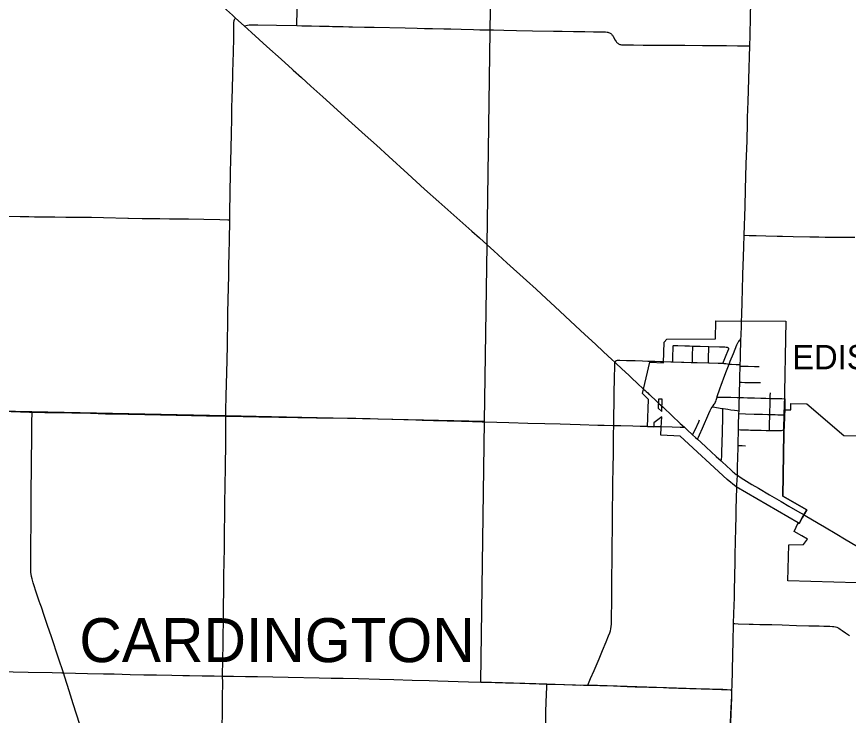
# Model space of a CAD drawing. Extents: x 9078 to 9739, y 4248 to 4966.
# Drawn here: x 9264.8 to 9349.9, y 4628.2 to 4699.7 of the extents above; entities that cross this region are included whole.
import ezdxf

# ---------------------------------------------------------------- set-up
doc = ezdxf.new("R2010")
doc.units = 0
for name, color, linetype in [('GM_X_City_Street', 7, 'Continuous'), ('GM_X_Corporation', 7, 'Continuous'), ('GM_X_Corporation_Text', 7, 'Continuous'), ('GM_X_County_Road', 7, 'Continuous'), ('GM_X_State_Route', 7, 'Continuous'), ('GM_X_Township', 7, 'Continuous'), ('GM_X_Township_Road', 7, 'Continuous'), ('GM_X_Township_Text', 7, 'Continuous')]:
    doc.layers.add(name, color=color, linetype=linetype)

msp = doc.modelspace()

# ---------------------------------------------------------------- linework, layer by layer
at = {"layer": 'GM_X_City_Street'}
for points in [[(9338.904, 4666.691), (9338.915, 4666.982), (9338.956, 4668.127), (9338.963, 4668.547)], [(9337.689, 4664.123), (9337.806, 4664.403), (9338.137, 4665.214), (9338.487, 4666.069), (9338.585, 4666.294), (9338.624, 4666.366), (9338.669, 4666.434), (9338.748, 4666.533), (9338.813, 4666.611), (9338.904, 4666.691)], [(9338.832, 4664.058), (9338.846, 4664.612), (9338.863, 4665.347), (9338.887, 4666.246), (9338.904, 4666.691)], [(9331.929, 4664.354), (9331.932, 4664.478), (9331.949, 4665.054), (9331.963, 4665.624), (9331.971, 4665.911), (9331.971, 4665.932), (9331.973, 4665.952), (9331.978, 4665.97), (9331.984, 4665.986), (9331.994, 4666.001)], [(9331.994, 4666.001), (9332.004, 4666.011), (9332.016, 4666.018), (9332.032, 4666.023), (9332.051, 4666.025), (9332.077, 4666.026), (9332.434, 4666.016), (9333.152, 4665.988), (9333.629, 4665.969), (9333.974, 4665.955)], [(9333.947, 4664.285), (9333.946, 4664.411), (9333.944, 4664.671), (9333.946, 4664.923), (9333.951, 4665.188), (9333.967, 4665.669), (9333.971, 4665.832), (9333.974, 4665.955)], [(9333.974, 4665.955), (9334.721, 4665.935), (9335.625, 4665.91)], [(9335.568, 4664.233), (9335.57, 4664.359), (9335.571, 4664.498), (9335.58, 4664.741), (9335.617, 4665.758), (9335.625, 4665.91)], [(9335.625, 4665.91), (9336.724, 4665.88), (9337.253, 4665.865), (9337.377, 4665.862), (9337.423, 4665.859), (9337.461, 4665.854), (9337.495, 4665.843), (9337.529, 4665.828), (9337.566, 4665.801), (9337.593, 4665.77), (9337.612, 4665.735), (9337.621, 4665.696), (9337.622, 4665.655), (9337.618, 4665.616), (9337.606, 4665.575), (9337.301, 4664.816), (9337.081, 4664.303), (9337.033, 4664.194)], [(9330.996, 4664.388), (9331.718, 4664.361), (9331.929, 4664.354)], [(9331.929, 4664.354), (9332.825, 4664.324), (9333.064, 4664.315), (9333.801, 4664.29), (9333.947, 4664.285)], [(9333.947, 4664.285), (9334.433, 4664.267), (9335.568, 4664.233)], [(9335.568, 4664.233), (9335.656, 4664.231), (9336.559, 4664.204), (9336.884, 4664.198), (9337.033, 4664.194)], [(9336.469, 4660.748), (9336.483, 4660.795), (9336.752, 4661.568), (9336.926, 4662.066), (9336.989, 4662.247), (9337.154, 4662.72), (9337.207, 4662.873), (9337.344, 4663.266), (9337.617, 4663.95), (9337.689, 4664.123)], [(9337.033, 4664.194), (9337.158, 4664.191), (9337.366, 4664.169), (9337.54, 4664.144), (9337.689, 4664.123)], [(9337.689, 4664.123), (9337.757, 4664.113), (9337.939, 4664.095), (9338.427, 4664.079), (9338.673, 4664.066), (9338.832, 4664.058)], [(9338.785, 4662.257), (9338.8, 4662.731), (9338.829, 4663.907)], [(9338.829, 4663.907), (9338.832, 4664.058)], [(9338.829, 4663.907), (9338.948, 4663.905), (9339.654, 4663.893), (9340.274, 4663.882), (9340.504, 4663.878), (9340.778, 4663.875)], [(9338.745, 4660.7), (9338.753, 4661.004), (9338.757, 4661.177), (9338.763, 4661.381), (9338.768, 4661.603), (9338.777, 4661.937), (9338.785, 4662.257)], [(9338.785, 4662.257), (9338.963, 4662.251), (9339.309, 4662.246), (9339.657, 4662.241), (9340.017, 4662.236), (9340.334, 4662.231), (9340.642, 4662.227), (9340.901, 4662.223)], [(9341.896, 4660.604), (9341.897, 4660.697), (9341.903, 4660.859), (9341.911, 4661.184)], [(9335.987, 4659.746), (9336.054, 4659.835), (9336.17, 4660.013), (9336.217, 4660.093), (9336.265, 4660.178), (9336.322, 4660.304), (9336.365, 4660.424), (9336.469, 4660.748)], [(9336.469, 4660.748), (9336.629, 4660.744), (9337.127, 4660.732), (9337.875, 4660.723), (9338.528, 4660.706), (9338.654, 4660.702), (9338.745, 4660.7)], [(9338.703, 4659.337), (9338.713, 4659.666), (9338.722, 4659.949), (9338.733, 4660.327), (9338.745, 4660.7)], [(9338.745, 4660.7), (9339.014, 4660.69), (9339.179, 4660.684), (9339.579, 4660.672), (9340.026, 4660.659), (9340.295, 4660.651), (9340.937, 4660.632), (9341.458, 4660.617), (9341.896, 4660.604)], [(9341.858, 4658.966), (9341.859, 4658.989), (9341.873, 4659.504), (9341.879, 4659.721), (9341.886, 4659.951), (9341.89, 4660.212), (9341.894, 4660.49), (9341.896, 4660.604)], [(9341.896, 4660.604), (9342.257, 4660.597), (9342.561, 4660.591), (9343.069, 4660.58), (9343.412, 4660.574)], [(9343.425, 4659.449), (9343.428, 4659.662), (9343.427, 4659.89), (9343.42, 4660.289), (9343.412, 4660.574)], [(9334.441, 4656.443), (9334.523, 4656.586), (9334.564, 4656.656), (9334.672, 4656.876), (9334.972, 4657.548), (9335.613, 4659.054), (9335.75, 4659.351), (9335.866, 4659.567), (9335.955, 4659.704), (9335.987, 4659.746)], [(9335.987, 4659.746), (9336.215, 4659.707), (9336.397, 4659.676), (9336.592, 4659.642), (9336.761, 4659.613), (9336.959, 4659.578), (9337.072, 4659.559)], [(9336.875, 4654.208), (9336.907, 4654.376), (9336.925, 4654.467), (9336.939, 4654.583), (9336.958, 4655.073), (9336.985, 4656.138), (9337.01, 4657.114), (9337.016, 4657.51), (9337.034, 4658.325), (9337.051, 4658.896), (9337.06, 4659.19), (9337.066, 4659.385), (9337.072, 4659.559)], [(9337.072, 4659.559), (9337.546, 4659.492), (9337.859, 4659.451), (9338.228, 4659.402), (9338.513, 4659.363), (9338.703, 4659.337)], [(9338.695, 4659.062), (9338.703, 4659.337)], [(9343.393, 4658.923), (9343.405, 4659.038), (9343.416, 4659.237), (9343.421, 4659.328), (9343.425, 4659.449)], [(9333.954, 4656.887), (9334.004, 4656.982), (9334.098, 4657.158), (9334.21, 4657.38), (9334.591, 4658.21), (9334.632, 4658.311), (9334.677, 4658.419)], [(9338.654, 4657.407), (9338.668, 4657.873), (9338.695, 4659.062)], [(9338.695, 4659.062), (9339.364, 4659.033), (9340.269, 4659.004), (9341.091, 4658.988), (9341.668, 4658.973), (9341.858, 4658.966)], [(9341.814, 4657.324), (9341.817, 4657.459), (9341.822, 4657.619), (9341.828, 4657.836), (9341.834, 4658.058), (9341.84, 4658.297), (9341.845, 4658.488), (9341.851, 4658.691), (9341.858, 4658.966)], [(9341.858, 4658.966), (9342.171, 4658.955), (9342.406, 4658.946), (9342.665, 4658.939), (9342.934, 4658.932), (9343.135, 4658.927), (9343.342, 4658.924), (9343.393, 4658.923)], [(9343.251, 4657.387), (9343.291, 4657.426), (9343.321, 4657.479), (9343.342, 4657.549), (9343.345, 4657.632), (9343.359, 4657.956), (9343.378, 4658.54), (9343.383, 4658.72), (9343.386, 4658.833), (9343.393, 4658.923)], [(9330.764, 4657.724), (9331.866, 4657.688), (9332.683, 4657.656), (9332.941, 4657.657), (9333.118, 4657.658)], [(9338.614, 4655.802), (9338.618, 4655.994), (9338.632, 4656.532), (9338.639, 4656.801), (9338.645, 4657.04), (9338.654, 4657.407)], [(9338.654, 4657.407), (9338.843, 4657.4), (9339.337, 4657.383), (9339.661, 4657.375), (9339.873, 4657.369), (9340.286, 4657.359), (9340.637, 4657.35), (9340.98, 4657.341), (9341.47, 4657.329), (9341.814, 4657.324)], [(9341.814, 4657.324), (9342.37, 4657.315), (9342.864, 4657.309), (9342.965, 4657.314), (9343.065, 4657.322), (9343.169, 4657.348), (9343.251, 4657.387)], [(9338.535, 4652.744), (9338.554, 4653.38), (9338.59, 4654.813), (9338.603, 4655.334), (9338.614, 4655.802)], [(9338.614, 4655.802), (9338.756, 4655.797), (9339.034, 4655.789), (9339.355, 4655.768)], [(9338.488, 4651.53), (9338.495, 4651.748), (9338.513, 4652.237), (9338.534, 4652.727), (9338.535, 4652.744)]]:
    msp.add_lwpolyline(points, dxfattribs=at)
at = {"layer": 'GM_X_Corporation'}
for points in [[(9328.825, 4661.1), (9329.593, 4664.295), (9330.973, 4664.234), (9331.038, 4666.359), (9331.332, 4666.667), (9336.306, 4666.695), (9336.326, 4668.551), (9343.479, 4668.515), (9343.327, 4659.441), (9343.287, 4657.058), (9343.178, 4650.605), (9345.645, 4649.194), (9345.18, 4648.372), (9344.866, 4647.818), (9344.771, 4647.873), (9338.422, 4651.547), (9337.509, 4652.301), (9332.684, 4656.738), (9330.708, 4656.831), (9330.741, 4657.643), (9330.804, 4658.725), (9330.006, 4658.093), (9329.992, 4657.666), (9329.337, 4657.686), (9329.434, 4660.501)], [(9330.435, 4659.589), (9330.82, 4659.248), (9330.859, 4660.529), (9330.458, 4660.539)]]:
    msp.add_lwpolyline(points, close=True, dxfattribs=at)
msp.add_lwpolyline([(9350.749, 4641.741), (9343.698, 4641.93), (9343.788, 4645.611), (9345.316, 4645.655), (9345.71, 4646.215), (9345.141, 4646.543), (9344.361, 4646.993), (9344.771, 4647.873), (9344.866, 4647.818), (9345.18, 4648.372), (9345.645, 4649.194), (9343.178, 4650.605), (9343.287, 4657.058), (9343.327, 4659.441), (9343.994, 4659.433), (9344.001, 4660.084), (9345.652, 4660.064), (9349.423, 4656.821), (9370.603, 4656.531)], dxfattribs=at)
at = {"layer": 'GM_X_County_Road'}
for points in [[(9339.809, 4696.668), (9339.841, 4697.707), (9339.885, 4699.675), (9339.91, 4701.069), (9339.941, 4704.267), (9339.928, 4706.482), (9339.916, 4708.778), (9339.909, 4710.91), (9339.911, 4710.962)], [(9286.608, 4678.869), (9286.623, 4679.683), (9286.655, 4681.567), (9286.691, 4683.709), (9286.719, 4685.02), (9286.739, 4686.079), (9286.779, 4687.811), (9286.814, 4689.114), (9286.83, 4690.185), (9286.866, 4691.497), (9286.874, 4692.07), (9286.89, 4692.655), (9286.918, 4693.377), (9286.93, 4694.115), (9286.95, 4694.857), (9286.986, 4696.16), (9287.014, 4697.319), (9287.038, 4698.542), (9287.04, 4699.038), (9287.065, 4699.272), (9287.093, 4699.368), (9287.142, 4699.433), (9287.207, 4699.513)], [(9288.083, 4698.718), (9288.275, 4698.765), (9288.434, 4698.803), (9288.596, 4698.823), (9288.841, 4698.833), (9289.496, 4698.825), (9291.377, 4698.786), (9293.471, 4698.744)], [(9293.471, 4698.744), (9293.993, 4698.729), (9294.975, 4698.712), (9295.792, 4698.697), (9296.283, 4698.686), (9296.446, 4698.682), (9296.772, 4698.672), (9297.102, 4698.664), (9297.445, 4698.656), (9297.81, 4698.648), (9298.205, 4698.639), (9298.773, 4698.625), (9299.154, 4698.616), (9300.383, 4698.591), (9301.366, 4698.582), (9304.562, 4698.507), (9305.791, 4698.478), (9306.528, 4698.458), (9307.347, 4698.435), (9308.495, 4698.414), (9309.232, 4698.399), (9310.297, 4698.374), (9311.526, 4698.346), (9312.182, 4698.326), (9312.919, 4698.307), (9313.244, 4698.302)], [(9313.244, 4698.302), (9313.575, 4698.296), (9314.64, 4698.273), (9315.951, 4698.246), (9317.59, 4698.217), (9319.721, 4698.182), (9320.622, 4698.167), (9321.769, 4698.156), (9322.916, 4698.127), (9323.818, 4698.118), (9324.884, 4698.106), (9325.047, 4698.097), (9325.21, 4698.077), (9325.291, 4698.06), (9325.369, 4698.037), (9325.446, 4698.008), (9325.519, 4697.971), (9325.587, 4697.927), (9325.65, 4697.875), (9325.708, 4697.816), (9325.757, 4697.752), (9325.843, 4697.612), (9326.038, 4697.251), (9326.128, 4697.114), (9326.18, 4697.051), (9326.238, 4696.993), (9326.301, 4696.94), (9326.368, 4696.894), (9326.441, 4696.856), (9326.517, 4696.826), (9326.596, 4696.805), (9326.676, 4696.791), (9326.922, 4696.773), (9327.25, 4696.769), (9327.905, 4696.766), (9328.889, 4696.756), (9331.676, 4696.741), (9333.151, 4696.731), (9334.954, 4696.714), (9336.347, 4696.701), (9337.412, 4696.691), (9338.56, 4696.684), (9339.216, 4696.683), (9339.543, 4696.674), (9339.731, 4696.67), (9339.809, 4696.668)], [(9339.225, 4677.29), (9339.32, 4680.245), (9339.377, 4681.966), (9339.452, 4684.59), (9339.527, 4686.967), (9339.578, 4688.771), (9339.588, 4689.346), (9339.627, 4690.985), (9339.705, 4693.28), (9339.809, 4696.668)], [(9286.208, 4658.784), (9286.21, 4659.009), (9286.214, 4659.419), (9286.245, 4660.813), (9286.277, 4662.126), (9286.301, 4663.192), (9286.361, 4665.981), (9286.383, 4666.965), (9286.398, 4667.868), (9286.425, 4669.344), (9286.47, 4671.969), (9286.498, 4673.118), (9286.516, 4674.102), (9286.541, 4675.497), (9286.566, 4676.727), (9286.608, 4678.869)], [(9338.963, 4668.547), (9338.978, 4669.085), (9339.021, 4670.562), (9339.061, 4671.628), (9339.104, 4673.269), (9339.159, 4675.074), (9339.192, 4676.141), (9339.225, 4677.29)], [(9259.739, 4659.34), (9261.688, 4659.302), (9264.23, 4659.252), (9266.116, 4659.207), (9266.386, 4659.201)], [(9266.386, 4659.201), (9267.674, 4659.174), (9268.985, 4659.148), (9270.461, 4659.119), (9272.347, 4659.08), (9273.905, 4659.043), (9275.299, 4659.012), (9276.201, 4658.994), (9277.923, 4658.96), (9281.121, 4658.892), (9284.237, 4658.833), (9286.208, 4658.784)], [(9286.208, 4658.784), (9286.368, 4658.781), (9289.566, 4658.723), (9291.616, 4658.686), (9293.584, 4658.648), (9295.47, 4658.619), (9296.481, 4658.612)], [(9296.481, 4658.612), (9297.193, 4658.607), (9299.489, 4658.571), (9300.965, 4658.55), (9301.785, 4658.531), (9303.178, 4658.484), (9305.638, 4658.416), (9306.276, 4658.39)], [(9306.276, 4658.39), (9306.703, 4658.372), (9307.44, 4658.34), (9308.834, 4658.304), (9310.309, 4658.27), (9311.457, 4658.242), (9312.441, 4658.218), (9312.665, 4658.212)], [(9312.665, 4658.212), (9313.917, 4658.174), (9315.146, 4658.136), (9317.114, 4658.084), (9318.836, 4658.034), (9320.393, 4657.991), (9322.442, 4657.926), (9324.246, 4657.874), (9324.901, 4657.854), (9325.803, 4657.834), (9325.891, 4657.833)], [(9325.891, 4657.833), (9326.623, 4657.823), (9327.853, 4657.79), (9328.591, 4657.781), (9329.358, 4657.761)], [(9329.358, 4657.761), (9330.011, 4657.745)], [(9330.011, 4657.745), (9330.397, 4657.734), (9330.764, 4657.724)], [(9338.156, 4637.569), (9338.177, 4638.605), (9338.228, 4640.246), (9338.236, 4640.739), (9338.282, 4642.626), (9338.304, 4643.692), (9338.325, 4644.676), (9338.353, 4645.907), (9338.393, 4647.384), (9338.412, 4648.451), (9338.423, 4649.353), (9338.452, 4650.337), (9338.488, 4651.53)], [(9337.976, 4630.791), (9337.989, 4631.139), (9338.031, 4632.862), (9338.105, 4635.816), (9338.153, 4637.456), (9338.156, 4637.569)], [(9337.163, 4610.641), (9337.194, 4611.457), (9337.248, 4612.852), (9337.266, 4613.282), (9337.286, 4613.743), (9337.301, 4614.099), (9337.33, 4614.694), (9337.361, 4615.362), (9337.402, 4616.213), (9337.494, 4618.509), (9337.564, 4620.067), (9337.625, 4621.789), (9337.671, 4622.773), (9337.725, 4624.167), (9337.749, 4624.821), (9337.761, 4625.151), (9337.79, 4625.971), (9337.842, 4627.366), (9337.88, 4628.35), (9337.953, 4630.154), (9337.976, 4630.791)]]:
    msp.add_lwpolyline(points, dxfattribs=at)
at = {"layer": 'GM_X_State_Route'}
for points in [[(9283.058, 4703.341), (9283.803, 4702.644), (9284.888, 4701.642), (9286.274, 4700.363), (9286.88, 4699.81), (9287.207, 4699.513), (9288.083, 4698.718), (9288.824, 4698.046), (9290.407, 4696.617), (9291.872, 4695.301), (9293.04, 4694.242)], [(9293.04, 4694.242), (9293.087, 4694.199), (9293.942, 4693.432), (9294.913, 4692.549), (9296.132, 4691.451), (9299.111, 4688.753), (9300.455, 4687.548), (9301.619, 4686.511), (9302.89, 4685.349), (9304.822, 4683.571), (9306.519, 4682.025), (9307.985, 4680.71), (9309.217, 4679.627), (9311.365, 4677.722), (9312.164, 4677.015), (9312.927, 4676.325), (9313.624, 4675.694), (9314.964, 4674.486), (9316.968, 4672.666), (9317.938, 4671.78), (9319.023, 4670.779), (9319.869, 4670.002), (9321.967, 4668.042), (9322.925, 4667.145), (9324.012, 4666.146), (9324.85, 4665.36), (9325.688, 4664.575), (9325.999, 4664.308), (9326.103, 4664.212), (9326.732, 4663.617), (9327.425, 4662.972)], [(9327.425, 4662.972), (9327.728, 4662.69), (9328.285, 4662.171), (9328.949, 4661.549)], [(9328.949, 4661.549), (9329.101, 4661.407), (9329.207, 4661.309), (9329.369, 4661.158), (9329.528, 4661.01), (9329.567, 4660.973)], [(9329.567, 4660.973), (9330.247, 4660.333), (9330.517, 4660.084)], [(9330.517, 4660.084), (9330.929, 4659.705), (9330.966, 4659.67)], [(9330.966, 4659.67), (9332.692, 4658.05), (9332.905, 4657.854)], [(9332.905, 4657.854), (9333.118, 4657.658), (9333.414, 4657.385), (9333.954, 4656.887), (9334.257, 4656.613), (9334.441, 4656.443), (9334.797, 4656.115), (9335.34, 4655.617), (9336.361, 4654.675), (9336.875, 4654.208), (9336.966, 4654.126), (9337.864, 4653.295), (9338.077, 4653.108), (9338.16, 4653.039), (9338.255, 4652.961), (9338.429, 4652.826), (9338.535, 4652.744), (9338.913, 4652.491), (9340.029, 4651.809), (9340.681, 4651.416), (9341.822, 4650.748), (9343.012, 4650.045), (9343.788, 4649.591), (9344.704, 4649.06), (9345.365, 4648.678)], [(9345.365, 4648.678), (9345.457, 4648.622), (9346.797, 4647.828), (9347.433, 4647.455), (9348.703, 4646.704), (9349.484, 4646.253), (9350.828, 4645.465)]]:
    msp.add_lwpolyline(points, dxfattribs=at)
at = {"layer": 'GM_X_Township'}
for points in [[(9313.407, 4711.5), (9313.217, 4698.184), (9312.905, 4676.328), (9312.647, 4658.232), (9286.19, 4658.812), (9266.36, 4659.236), (9259.712, 4659.36), (9239.857, 4659.743), (9233.221, 4659.857), (9219.983, 4660.048), (9213.36, 4660.133), (9206.245, 4660.249)], [(9312.647, 4658.232), (9312.261, 4631.593), (9319.031, 4631.42), (9322.506, 4631.285), (9323.21, 4631.298), (9334.307, 4630.93), (9337.049, 4630.853), (9337.941, 4630.782), (9337.951, 4630.023), (9337.165, 4610.668), (9336.171, 4584.222), (9335.616, 4570.813), (9334.675, 4553.48)]]:
    msp.add_lwpolyline(points, dxfattribs=at)
at = {"layer": 'GM_X_Township_Road'}
for points in [[(9293.471, 4698.744), (9293.501, 4700.364), (9293.527, 4701.593), (9293.629, 4705.689), (9293.745, 4710.277), (9293.779, 4711.983)], [(9260.091, 4679.312), (9260.319, 4679.304), (9260.401, 4679.303), (9261.468, 4679.276), (9262.535, 4679.262), (9265.161, 4679.222), (9266.064, 4679.206), (9266.638, 4679.196), (9268.526, 4679.169), (9268.727, 4679.167)], [(9268.727, 4679.167), (9269.84, 4679.15), (9270.661, 4679.143), (9271.563, 4679.134), (9272.466, 4679.131), (9273.697, 4679.107), (9276.175, 4679.051)], [(9276.175, 4679.051), (9276.241, 4679.049), (9277.636, 4679.023), (9279.442, 4679.002), (9280.427, 4678.989), (9281.494, 4678.975), (9282.397, 4678.965), (9283.957, 4678.942), (9285.598, 4678.902), (9286.419, 4678.876), (9286.608, 4678.869)], [(9339.225, 4677.29), (9339.733, 4677.278), (9340.464, 4677.258), (9341.447, 4677.235), (9342.594, 4677.201), (9343.168, 4677.189), (9344.233, 4677.16), (9345.955, 4677.132), (9346.856, 4677.12), (9347.512, 4677.113), (9348.414, 4677.105), (9349.151, 4677.098), (9350.545, 4677.086)], [(9325.999, 4664.308), (9326.061, 4664.386), (9326.12, 4664.446), (9326.162, 4664.473), (9326.208, 4664.492), (9326.269, 4664.502), (9326.345, 4664.507), (9326.513, 4664.505), (9327.206, 4664.497), (9328.076, 4664.47), (9328.836, 4664.446), (9329.381, 4664.429), (9329.63, 4664.418)], [(9329.63, 4664.418), (9330.077, 4664.408), (9330.663, 4664.395), (9330.996, 4664.388)], [(9325.891, 4657.833), (9325.903, 4658.339), (9325.906, 4658.995), (9325.918, 4659.98), (9325.932, 4661.128), (9325.967, 4662.687), (9325.988, 4663.918), (9325.999, 4664.308)], [(9267.217, 4639.605), (9267.126, 4639.871), (9266.887, 4640.57), (9266.509, 4641.741), (9266.393, 4642.135), (9266.337, 4642.374), (9266.298, 4642.617), (9266.275, 4642.786), (9266.268, 4642.943), (9266.257, 4643.271), (9266.266, 4644.009), (9266.274, 4644.912), (9266.275, 4646.306), (9266.277, 4647.209), (9266.284, 4648.275), (9266.288, 4648.931), (9266.29, 4649.751), (9266.293, 4650.654), (9266.302, 4651.802), (9266.314, 4652.786), (9266.327, 4654.017), (9266.357, 4656.724), (9266.372, 4658.447), (9266.38, 4658.896), (9266.382, 4659.021), (9266.386, 4659.201)], [(9285.882, 4632.201), (9285.882, 4632.265), (9285.896, 4633.824), (9285.918, 4635.547), (9285.93, 4636.367), (9285.952, 4637.762), (9285.977, 4639.239), (9286.003, 4641.045), (9286.018, 4642.604), (9286.032, 4643.753), (9286.054, 4645.394), (9286.073, 4647.035), (9286.105, 4648.676), (9286.12, 4649.825), (9286.138, 4651.712), (9286.162, 4653.518), (9286.192, 4656.144), (9286.206, 4658.114), (9286.207, 4658.494), (9286.208, 4658.784)], [(9325.692, 4641.29), (9325.696, 4642.509), (9325.72, 4643.821), (9325.741, 4645.872), (9325.753, 4647.02), (9325.762, 4648.497), (9325.765, 4649.235), (9325.789, 4650.958), (9325.804, 4651.942), (9325.831, 4653.5), (9325.85, 4654.977), (9325.868, 4656.289), (9325.877, 4657.027), (9325.889, 4657.766), (9325.891, 4657.833)], [(9323.234, 4631.265), (9323.517, 4631.94), (9323.87, 4632.77), (9324.382, 4633.979), (9324.73, 4634.811), (9325.114, 4635.718), (9325.366, 4636.324), (9325.491, 4636.628), (9325.56, 4636.819), (9325.608, 4637.027), (9325.638, 4637.257), (9325.656, 4637.508), (9325.663, 4637.997), (9325.681, 4640.047), (9325.691, 4641.278), (9325.692, 4641.29)], [(9269.594, 4632.521), (9269.096, 4634.043), (9268.367, 4636.221), (9267.967, 4637.385), (9267.618, 4638.393), (9267.338, 4639.251), (9267.217, 4639.605)], [(9338.156, 4637.569), (9338.277, 4637.563), (9338.605, 4637.545), (9339.754, 4637.51), (9340.165, 4637.498), (9340.822, 4637.483), (9342.054, 4637.458), (9343.121, 4637.425), (9344.599, 4637.382), (9345.831, 4637.352), (9346.241, 4637.342), (9346.897, 4637.323), (9347.389, 4637.305), (9347.98, 4637.29), (9348.268, 4637.275), (9348.409, 4637.265), (9348.571, 4637.238), (9348.725, 4637.192), (9348.844, 4637.143), (9348.927, 4637.1), (9349.067, 4637.007), (9349.271, 4636.869), (9349.605, 4636.631), (9349.999, 4636.335)], [(9259.608, 4632.716), (9260.011, 4632.716), (9261.815, 4632.681), (9262.881, 4632.662), (9264.439, 4632.63), (9265.998, 4632.596), (9268.458, 4632.548), (9269.442, 4632.524), (9269.594, 4632.521)], [(9269.594, 4632.521), (9272.066, 4632.462), (9273.676, 4632.431), (9274.772, 4632.412), (9276.412, 4632.367), (9277.806, 4632.339), (9279.118, 4632.326), (9280.676, 4632.289), (9281.824, 4632.257), (9282.48, 4632.245), (9283.792, 4632.233), (9285.022, 4632.212), (9285.882, 4632.201)], [(9273.897, 4619.017), (9272.915, 4622.087), (9272.492, 4623.416), (9271.76, 4625.68), (9271.263, 4627.243), (9270.597, 4629.356), (9270.179, 4630.686), (9269.734, 4632.094), (9269.594, 4632.521)], [(9285.417, 4605.569), (9285.426, 4605.761), (9285.43, 4605.843), (9285.452, 4606.664), (9285.489, 4608.223), (9285.52, 4609.536), (9285.539, 4610.602), (9285.554, 4611.341), (9285.575, 4612.161), (9285.591, 4612.981), (9285.61, 4614.212), (9285.636, 4615.771), (9285.665, 4617.248), (9285.71, 4619.628), (9285.748, 4621.761), (9285.764, 4622.746), (9285.774, 4623.567), (9285.788, 4624.551), (9285.822, 4626.684), (9285.85, 4628.736), (9285.867, 4630.049), (9285.884, 4631.526), (9285.882, 4632.201)], [(9285.882, 4632.201), (9285.924, 4632.2), (9286.99, 4632.187), (9288.22, 4632.166), (9289.451, 4632.142), (9292.567, 4632.085), (9295.765, 4632.02), (9296.996, 4632.001), (9297.287, 4631.995)], [(9297.287, 4631.995), (9298.226, 4631.977), (9299.784, 4631.946), (9301.916, 4631.898), (9303.391, 4631.84), (9305.277, 4631.776), (9306.998, 4631.73), (9307.9, 4631.703), (9311.016, 4631.619), (9312.279, 4631.584)], [(9312.279, 4631.584), (9312.706, 4631.577), (9314.827, 4631.501), (9316.296, 4631.458), (9318.255, 4631.411), (9319.051, 4631.387)], [(9318.725, 4620.057), (9318.74, 4620.724), (9318.768, 4621.953), (9318.792, 4622.69), (9318.834, 4624.082), (9318.879, 4626.048), (9318.926, 4627.604), (9318.953, 4628.587), (9319.008, 4630.389), (9319.035, 4631.045), (9319.051, 4631.387)], [(9319.051, 4631.387), (9319.735, 4631.368), (9321.961, 4631.291), (9322.786, 4631.269), (9323.234, 4631.265)], [(9323.234, 4631.265), (9323.652, 4631.252), (9324.473, 4631.225), (9325.871, 4631.183), (9327.268, 4631.131), (9328.09, 4631.103), (9328.911, 4631.082), (9329.487, 4631.068), (9330.062, 4631.053), (9330.966, 4631.033), (9331.541, 4631.011), (9332.528, 4630.978), (9335.98, 4630.87), (9337.788, 4630.799), (9337.976, 4630.791)]]:
    msp.add_lwpolyline(points, dxfattribs=at)

# ---------------------------------------------------------------- texts
at = {"layer": 'GM_X_Corporation_Text'}
msp.add_text('EDISON', height=2.5, rotation=0.00001, dxfattribs=at).set_placement((9344.151, 4663.581))
at = {"layer": 'GM_X_Township_Text'}
msp.add_text('CARDINGTON', height=4.5, rotation=0.00001, dxfattribs=at).set_placement((9271.218, 4633.623))

doc.saveas('drawing.dxf')
